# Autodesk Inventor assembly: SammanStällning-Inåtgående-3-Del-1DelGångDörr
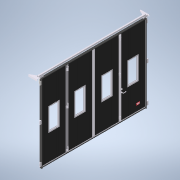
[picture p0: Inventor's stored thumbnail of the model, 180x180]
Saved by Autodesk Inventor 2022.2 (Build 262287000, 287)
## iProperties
Created: 2022-02
Part Number: SammanStällning-Inåtgående-3-Del-1DelGångDörr
Document SubType Name: Assembly
Designer: cl
Author: cl
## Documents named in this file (20)
- G:\AutoCad\Carl Lund\3D-modeller systemlösningar\3D-modell-systemlösning-2022\SammanStällning-Inåtgående-3-Del-1DelGångDörr.iam
- G:\AutoCad\Carl Lund\3D-modeller systemlösningar\3D-modell-systemlösning-2022\Parts\BladKomplett2022.iam
- G:\AutoCad\Carl Lund\3D-modeller systemlösningar\3D-modell-systemlösning-2022\Parts\MellanGångjärnH.ipt
- G:\AutoCad\Carl Lund\3D-modeller systemlösningar\3D-modell-systemlösning-2022\Parts\MellanGångjärnV.ipt
- G:\AutoCad\Carl Lund\3D-modeller systemlösningar\3D-modell-systemlösning-2022\Parts\Karmstyrning.ipt
- G:\AutoCad\Carl Lund\3D-modeller systemlösningar\3D-modell-systemlösning-2022\Parts\KarmgångjärnH.ipt
- G:\AutoCad\Carl Lund\3D-modeller systemlösningar\3D-modell-systemlösning-2022\Parts\KarmgångjärnV.ipt
- G:\AutoCad\Carl Lund\3D-modeller systemlösningar\3D-modell-systemlösning-2022\Parts\SidotätningUppe.ipt
- G:\AutoCad\Carl Lund\3D-modeller systemlösningar\3D-modell-systemlösning-2022\Parts\SidoTätning.ipt
- G:\AutoCad\Carl Lund\3D-modeller systemlösningar\3D-modell-systemlösning-2022\Parts\SläpList.ipt
- G:\AutoCad\Carl Lund\3D-modeller systemlösningar\3D-modell-systemlösning-2022\Parts\GummilistMellan.ipt
- G:\AutoCad\Carl Lund\3D-modeller systemlösningar\3D-modell-systemlösning-2022\Styrande.iam
- G:\AutoCad\Carl Lund\3D-modeller systemlösningar\3D-modell-systemlösning-2022\Parts\GarageregelHöger.ipt
- G:\AutoCad\Carl Lund\3D-modeller systemlösningar\3D-modell-systemlösning-2022\Parts\UppställningsbeslagHöger.ipt
- G:\AutoCad\Carl Lund\3D-modeller systemlösningar\3D-modell-systemlösning-2022\Parts\UppställningsbeslagVänster.ipt
- G:\AutoCad\Carl Lund\3D-modeller systemlösningar\3D-modell-systemlösning-2022\Parts\styrrulle.ipt
- G:\AutoCad\Carl Lund\3D-modeller systemlösningar\3D-modell-systemlösning-2022\Parts\Styrskena.ipt
- G:\AutoCad\Carl Lund\3D-modeller systemlösningar\3D-modell-systemlösning-2022\Parts\Anslagslist.ipt
- G:\AutoCad\Carl Lund\3D-modeller systemlösningar\3D-modell-systemlösning-2022\Parts\DörrHandtag-H.ipt
- G:\AutoCad\Carl Lund\3D-modeller systemlösningar\3D-modell-systemlösning-2022\Parts\Logga.ipt
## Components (41 placed, 18 different names)
1. DörrHandtag-H:1 — Mate:183, Mate:184, Mate:185, Mate:186
2. Logga:1 — Mate:187, Mate:188, Mate:189
3. BladKomplett2022:1 [sub-assembly] — Mate:1, Mate:2, Flush:1, Flush:2, Flush:3, Flush:8, Flush:28, Flush:29, Mate:28, Flush:30, Mate:42, Flush:73, Mate:39, Mate:43, Mate:47, Mate:48, Flush:99, Flush:100, Flush:101, Flush:102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
4. BladKomplett2022:2 [sub-assembly] — Flush:2, Flush:3, Flush:8, Flush:106, Mate:52, Flush:107, Flush:118, Flush:121, Mate:82, Flush:170, Flush:171, Mate:180, Mate:182, Flush:178
5. BladKomplett2022:3 [sub-assembly] — Flush:30, Flush:101, Flush:102, Mate:53, Flush:114, Flush:115
6. BladKomplett2022:4 [sub-assembly] — Flush:32, Flush:100, Flush:103, Mate:54, Flush:122, Flush:123, Flush:128, Mate:178
7. BladKomplett2022:5 [sub-assembly] — Flush:31, Flush:99, Flush:104, Flush:129, Mate:55, Flush:130, Mate:81, Flush:168, Flush:169, Mate:184
8. BladKomplett2022:6 [sub-assembly] — Mate:28, Flush:28, Flush:29, Flush:31, Flush:32, Mate:38, Flush:74, Mate:49, Mate:50, Flush:131, Flush:134, Flush:137, Mate:56, Flush:138, Flush:139, Mate:58, Mate:59, Flush:152, Mate:69, Mate:70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
9. GarageregelHöger:1 — Flush:156, Flush:157, Flush:158
10. GarageregelHöger:2 — Mate:77, Flush:154, Flush:155, Flush:156, Flush:157, Flush:158
11. Karmstyrning:2 — Mate:38, Mate:56, Flush:138, Flush:141
12. Karmstyrning:3 — Mate:39, Mate:43, Flush:140
13. Karmstyrning:4 — Mate:42, Mate:60, Mate:61, Flush:141
14. KarmgångjärnH:1 — Flush:74, Mate:49, Mate:50, Flush:166, Flush:167, Mate:80
15. KarmgångjärnV:1 — Flush:73, Mate:47, Mate:48, Flush:164, Flush:165, Mate:79
16. Karmstyrning:1 — Flush:139, Mate:58, Mate:59, Flush:140
17. MellanGångjärnV:3 — Flush:110, Flush:111, Flush:113
18. MellanGångjärnV:2 — Flush:108, Flush:109, Flush:110, Flush:111, Flush:112
19. MellanGångjärnV:1 — Flush:106, Mate:52, Flush:107, Flush:108, Flush:109
20. MellanGångjärnH:2 — Flush:116, Flush:117, Flush:118, Flush:119, Flush:120
21. MellanGångjärnH:3 — Flush:119, Flush:120, Flush:121
22. MellanGångjärnH:1 — Mate:53, Flush:114, Flush:115, Flush:116, Flush:117
23. MellanGångjärnV:6 — Flush:124, Flush:125, Flush:126, Flush:127, Flush:128
24. MellanGångjärnV:5 — Flush:126, Flush:127, Flush:129
25. MellanGångjärnV:4 — Mate:54, Flush:122, Flush:123, Flush:124, Flush:125
26. MellanGångjärnH:5 — Flush:132, Flush:133, Flush:134
27. MellanGångjärnH:6 — Flush:135, Flush:136, Flush:137
28. MellanGångjärnH:4 — Mate:55, Flush:130, Flush:131, Flush:132, Flush:133, Flush:135, Flush:136
29. GummilistMellan:5 — Mate:66, Flush:150, Flush:151
30. SidotätningUppe:1 — Mate:67, Mate:68, Flush:152, Mate:71, Mate:74
31. SidoTätning:1 — Mate:69, Mate:70, Mate:71, Mate:76
32. SidoTätning:2 — Mate:72, Mate:73, Mate:74
33. SläpList:1 — Mate:75, Flush:153, Mate:76, Mate:183
34. UppställningsbeslagVänster:1 — Flush:166, Flush:167, Mate:80
35. styrrulle:1 — Mate:81, Flush:168, Flush:169
36. styrrulle:2 — Mate:82, Flush:170, Flush:171, Tangent:1
37. Styrskena:1 — Mate:83, Flush:172, Tangent:1, Flush:174, Mate:176, Flush:175
38. Styrskena:2 — Flush:174, Mate:176, Flush:175
39. UppställningsbeslagHöger:1 — Flush:164, Flush:165, Mate:79, Mate:83, Flush:172
40. Anslagslist:1 — Mate:178, Mate:182, Flush:178
41. Anslagslist:2 — Mate:180, Mate:181, Flush:177
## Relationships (125: Flush 75, Mate 49, Tangent 1)
- Mate:1: BladKomplett2022:1
- Mate:2: BladKomplett2022:1
- Flush:1: BladKomplett2022:1
- Flush:2: BladKomplett2022:1 ↔ BladKomplett2022:2
- Flush:3: BladKomplett2022:1 ↔ BladKomplett2022:2
- Flush:8: BladKomplett2022:1 ↔ BladKomplett2022:2
- Mate:28: BladKomplett2022:1 ↔ BladKomplett2022:6
- Flush:28: BladKomplett2022:1 ↔ BladKomplett2022:6
- Flush:29: BladKomplett2022:1 ↔ BladKomplett2022:6
- Flush:30: BladKomplett2022:1 ↔ BladKomplett2022:3
- Flush:31: BladKomplett2022:5 ↔ BladKomplett2022:6
- Flush:32: BladKomplett2022:4 ↔ BladKomplett2022:6
- Mate:38: BladKomplett2022:6 ↔ Karmstyrning:2
- Mate:39: BladKomplett2022:1 ↔ Karmstyrning:3
- Mate:42: BladKomplett2022:1 ↔ Karmstyrning:4
- Mate:43: BladKomplett2022:1 ↔ Karmstyrning:3
- Flush:73: BladKomplett2022:1 ↔ KarmgångjärnV:1
- Mate:47: BladKomplett2022:1 ↔ KarmgångjärnV:1
- Mate:48: BladKomplett2022:1 ↔ KarmgångjärnV:1
- Flush:74: BladKomplett2022:6 ↔ KarmgångjärnH:1
- Mate:49: BladKomplett2022:6 ↔ KarmgångjärnH:1
- Mate:50: BladKomplett2022:6 ↔ KarmgångjärnH:1
- Flush:99: BladKomplett2022:1 ↔ BladKomplett2022:5
- Flush:100: BladKomplett2022:1 ↔ BladKomplett2022:4
- Flush:101: BladKomplett2022:1 ↔ BladKomplett2022:3
- Flush:102: BladKomplett2022:1 ↔ BladKomplett2022:3
- Flush:103: BladKomplett2022:1 ↔ BladKomplett2022:4
- Flush:104: BladKomplett2022:1 ↔ BladKomplett2022:5
- Flush:106: BladKomplett2022:2 ↔ MellanGångjärnV:1
- Mate:52: BladKomplett2022:2 ↔ MellanGångjärnV:1
- Flush:107: BladKomplett2022:2 ↔ MellanGångjärnV:1
- Flush:108: MellanGångjärnV:2 ↔ MellanGångjärnV:1
- Flush:109: MellanGångjärnV:2 ↔ MellanGångjärnV:1
- Flush:110: MellanGångjärnV:3 ↔ MellanGångjärnV:2
- Flush:111: MellanGångjärnV:3 ↔ MellanGångjärnV:2
- Flush:112: BladKomplett2022:1 ↔ MellanGångjärnV:2
- Flush:113: BladKomplett2022:1 ↔ MellanGångjärnV:3
- Mate:53: BladKomplett2022:3 ↔ MellanGångjärnH:1
- Flush:114: BladKomplett2022:3 ↔ MellanGångjärnH:1
- Flush:115: BladKomplett2022:3 ↔ MellanGångjärnH:1
- Flush:116: MellanGångjärnH:2 ↔ MellanGångjärnH:1
- Flush:117: MellanGångjärnH:2 ↔ MellanGångjärnH:1
- Flush:118: BladKomplett2022:2 ↔ MellanGångjärnH:2
- Flush:119: MellanGångjärnH:2 ↔ MellanGångjärnH:3
- Flush:120: MellanGångjärnH:2 ↔ MellanGångjärnH:3
- Flush:121: BladKomplett2022:2 ↔ MellanGångjärnH:3
- Mate:54: BladKomplett2022:4 ↔ MellanGångjärnV:4
- Flush:122: BladKomplett2022:4 ↔ MellanGångjärnV:4
- Flush:123: BladKomplett2022:4 ↔ MellanGångjärnV:4
- Flush:124: MellanGångjärnV:6 ↔ MellanGångjärnV:4
- Flush:125: MellanGångjärnV:6 ↔ MellanGångjärnV:4
- Flush:126: MellanGångjärnV:6 ↔ MellanGångjärnV:5
- Flush:127: MellanGångjärnV:6 ↔ MellanGångjärnV:5
- Flush:128: BladKomplett2022:4 ↔ MellanGångjärnV:6
- Flush:129: BladKomplett2022:5 ↔ MellanGångjärnV:5
- Mate:55: BladKomplett2022:5 ↔ MellanGångjärnH:4
- Flush:130: BladKomplett2022:5 ↔ MellanGångjärnH:4
- Flush:131: BladKomplett2022:6 ↔ MellanGångjärnH:4
- Flush:132: MellanGångjärnH:5 ↔ MellanGångjärnH:4
- Flush:133: MellanGångjärnH:5 ↔ MellanGångjärnH:4
- Flush:134: BladKomplett2022:6 ↔ MellanGångjärnH:5
- Flush:135: MellanGångjärnH:6 ↔ MellanGångjärnH:4
- Flush:136: MellanGångjärnH:6 ↔ MellanGångjärnH:4
- Flush:137: BladKomplett2022:6 ↔ MellanGångjärnH:6
- Mate:56: BladKomplett2022:6 ↔ Karmstyrning:2
- Flush:138: BladKomplett2022:6 ↔ Karmstyrning:2
- Flush:139: BladKomplett2022:6 ↔ Karmstyrning:1
- Mate:58: BladKomplett2022:6 ↔ Karmstyrning:1
- Mate:59: BladKomplett2022:6 ↔ Karmstyrning:1
- Flush:140: Karmstyrning:3 ↔ Karmstyrning:1
- Mate:60: BladKomplett2022:1 ↔ Karmstyrning:4
- Mate:61: BladKomplett2022:1 ↔ Karmstyrning:4
- Flush:141: Karmstyrning:2 ↔ Karmstyrning:4
- Mate:66: BladKomplett2022:1 ↔ GummilistMellan:5
- Flush:150: BladKomplett2022:1 ↔ GummilistMellan:5
- Flush:151: BladKomplett2022:1 ↔ GummilistMellan:5
- Mate:67: BladKomplett2022:1 ↔ SidotätningUppe:1
- Mate:68: BladKomplett2022:1 ↔ SidotätningUppe:1
- Flush:152: BladKomplett2022:6 ↔ SidotätningUppe:1
- Mate:69: BladKomplett2022:6 ↔ SidoTätning:1
- Mate:70: BladKomplett2022:6 ↔ SidoTätning:1
- Mate:71: SidotätningUppe:1 ↔ SidoTätning:1
- Mate:72: BladKomplett2022:1 ↔ SidoTätning:2
- Mate:73: BladKomplett2022:1 ↔ SidoTätning:2
- Mate:74: SidotätningUppe:1 ↔ SidoTätning:2
- Mate:75: BladKomplett2022:1 ↔ SläpList:1
- Flush:153: BladKomplett2022:1 ↔ SläpList:1
- Mate:76: SidoTätning:1 ↔ SläpList:1
- Mate:77: BladKomplett2022:1 ↔ GarageregelHöger:2
- Flush:154: BladKomplett2022:1 ↔ GarageregelHöger:2
- Flush:155: BladKomplett2022:1 ↔ GarageregelHöger:2
- Flush:156: GarageregelHöger:1 ↔ GarageregelHöger:2
- Flush:157: GarageregelHöger:1 ↔ GarageregelHöger:2
- Flush:158: GarageregelHöger:1 ↔ GarageregelHöger:2
- Flush:164: KarmgångjärnV:1 ↔ UppställningsbeslagHöger:1
- Flush:165: KarmgångjärnV:1 ↔ UppställningsbeslagHöger:1
- Mate:79: KarmgångjärnV:1 ↔ UppställningsbeslagHöger:1
- Flush:166: KarmgångjärnH:1 ↔ UppställningsbeslagVänster:1
- Flush:167: KarmgångjärnH:1 ↔ UppställningsbeslagVänster:1
- Mate:80: KarmgångjärnH:1 ↔ UppställningsbeslagVänster:1
- Mate:81: BladKomplett2022:5 ↔ styrrulle:1
- Flush:168: BladKomplett2022:5 ↔ styrrulle:1
- Flush:169: BladKomplett2022:5 ↔ styrrulle:1
- Mate:82: BladKomplett2022:2 ↔ styrrulle:2
- Flush:170: BladKomplett2022:2 ↔ styrrulle:2
- Flush:171: BladKomplett2022:2 ↔ styrrulle:2
- Mate:83: Styrskena:1 ↔ UppställningsbeslagHöger:1
- Flush:172: Styrskena:1 ↔ UppställningsbeslagHöger:1
- Tangent:1: styrrulle:2 ↔ Styrskena:1
- Flush:174: Styrskena:1 ↔ Styrskena:2
- Mate:176: Styrskena:1 ↔ Styrskena:2
- Flush:175: Styrskena:1 ↔ Styrskena:2
- Mate:178: BladKomplett2022:4 ↔ Anslagslist:1
- Mate:180: BladKomplett2022:2 ↔ Anslagslist:2
- Mate:181: BladKomplett2022:6 ↔ Anslagslist:2
- Flush:177: BladKomplett2022:6 ↔ Anslagslist:2
- Mate:182: BladKomplett2022:2 ↔ Anslagslist:1
- Flush:178: BladKomplett2022:2 ↔ Anslagslist:1
- Mate:183: DörrHandtag-H:1 ↔ SläpList:1
- Mate:184: DörrHandtag-H:1 ↔ BladKomplett2022:5
- Mate:185: DörrHandtag-H:1 ↔ BladKomplett2022:6
- Mate:186: DörrHandtag-H:1 ↔ BladKomplett2022:6
- Mate:187: Logga:1 ↔ BladKomplett2022:6
- Mate:188: Logga:1 ↔ BladKomplett2022:6
- Mate:189: Logga:1 ↔ BladKomplett2022:6
## Named parameters: Blad2 = 1012.5 mm, Blad3 = 0, Blad4 = 0, Blad5 = 1012.5 mm, MGJ12Djup = 0, MGJ12Bredd = 0, MGJ56Djup = 0, MGJ56Bredd = 0, MGJ23Djup = 48 mm, MGJ45Djup = 48 mm, GarageRegel5 = 0, GarageRegel6 = 0, BladBredd = 987.5 mm, Fönsterhöjd = 862 mm, Blad2_1 = 1012.5 mm, Blad3_1 = 0, Blad4_1 = 0, Blad5_1 = 1012.5 mm, Blad6 = 2025 mm, MGJ12Djup_1 = 0, MGJ12Bredd_1 = 0, MGJ2Djup = 0, MGJ2Bredd = 5012.5 mm, MGJ56Djup_1 = 0, MGJ56Bredd_1 = 0, MGJ23Djup_1 = 48 mm, MGJ45Djup_1 = 48 mm, GarageRegel5_1 = 0, GarageRegel6_1 = 0, Styrrulle2Djup = 0
